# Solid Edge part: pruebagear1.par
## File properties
Author: there
Template: SEER_ExtSpurGear.par
Last saved by: there
Revision: 2
Application: Solid Edge
Density: 7833.000 kg/m^3
Accuracy: 0.990
SEER_Parameters: SEERSG2#ER#3#ER#0.349065850398866#ER#0.003#ER#0.05#ER#0#ER#0.0002#ER#0#ER#1#ER#1.2#ER#0.8#ER#10000#ER#1#ER#1#ER#30#ER#90#ER#0.01#ER#0.02#ER#0.03#ER#0.03#ER#0#ER#0#ER#1000#ER#1000#ER#104.71975511966#ER#104.71975511966#ER#9.54#ER#9.54#ER#0.92#ER#1#ER#1#ER#1#ER#1#ER#0#ER#0#ER#1#ER#0#ER#0#ER#1#ER#0#ER#0#ER#0.08#ER#0.08#ER#0.008#ER#0.008#ER#0.025#ER#0.025#ER#0#ER#1140#ER#605#ER#0#ER#1140#ER#390#ER#11#ER#SweptProtrusion_1#ER#Pattern_1#ER#SweptProtrusion_1#ER#Pattern_1#ER##ER#C:\Users\there\Documents\CarroInertia\pruebagear2.par#ER#0#ER#0#ER#ExtrudedProtrusion_4#ER#ExtrudedCutout_5#ER#ExtrudedProtrusion_4#ER#ExtrudedCutout_5#ER#0#ER#1#ER#0#ER#0#ER#False#ER#0
Username: there
Material: Steel
Face Style: Steel
Fill Style: ANSI32(Steel)
Virtual Style: Machined steel
Coef. of Thermal Exp: 1.3e-05
Thermal Conductivity: 32.0
Specific Heat: 481.0
Modulus of Elasticity: 199947953000.0
Poission's Ratio: 0.29
Yield Stress: 262000766.0
Ultimate Stress: 358527364.0
Elongation: 0.0
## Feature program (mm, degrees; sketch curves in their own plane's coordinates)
sketch for "unnamed Protrusion 1" plane through (0, 0, 0) normal (0, 0, 1) x-axis (1, 0, 0)
  circle centre (0, 0) radius 11.027
extrude "unnamed Protrusion 1" add finite 30 along +normal
sketch for "unnamed Cutout 1" plane through (0, 0, 30) normal (0, 0, 1) x-axis (0, 1, 0)
extrude "unnamed Cutout 1" cut through along -normal
swept protrusion "ProtrusiónPorBarrido_1"
pattern "unnamed Pattern 1" of "ProtrusiónPorBarrido_1"
swept protrusion "unnamed SweptProtrusion 1"
swept protrusion "unnamed SweptProtrusion 2"
swept protrusion "unnamed SweptProtrusion 3"
swept protrusion "unnamed SweptProtrusion 4"
swept protrusion "unnamed SweptProtrusion 5"
swept protrusion "unnamed SweptProtrusion 6"
swept protrusion "unnamed SweptProtrusion 7"
swept protrusion "unnamed SweptProtrusion 8"
swept protrusion "unnamed SweptProtrusion 9"
swept protrusion "unnamed SweptProtrusion 10"
swept protrusion "unnamed SweptProtrusion 11"
swept protrusion "unnamed SweptProtrusion 12"
swept protrusion "unnamed SweptProtrusion 13"
swept protrusion "unnamed SweptProtrusion 14"
swept protrusion "unnamed SweptProtrusion 15"
swept protrusion "unnamed SweptProtrusion 16"
swept protrusion "unnamed SweptProtrusion 17"
swept protrusion "unnamed SweptProtrusion 18"
swept protrusion "unnamed SweptProtrusion 19"
base feature "unnamed BaseFeature 1"
sketch for "ProtrusiónExtruida_4" plane through (0, 0, 0) normal (0, 0, 1) x-axis (1, 0, 0)
  circle centre (0, 0) radius 12.5
extrude "ProtrusiónExtruida_4" add finite 30 along +normal
sketch for "VaciadoExtruido_5" plane through (0, 0, 0) normal (0, 0, 1) x-axis (1, 0, 0)
  circle centre (0, 0) radius 12.5
extrude "VaciadoExtruido_5" cut finite 30 along +normal
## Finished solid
Body 1: sheet body, 1 face, 2 edges, 0 vertices.
  Faces by surface: cylinder 1
  Edges by curve: circle 2
Body 2: solid body, 123 faces, 362 edges, 240 vertices.
  Faces by surface: spline 100, cylinder 21, plane 2
  Edges by curve: circle 162, spline 160, intersection 36, line 4
Bounding box of the edges (mm; curved faces can reach further): 27.679 x 27.679 x 30.000, from (-13.8395, -13.8395, 0) to (13.8395, 13.8395, 30).
Cylindrical faces by radius (mm): R5 x1, R11.027 x20, R12.5 x1
Planar faces by outward normal: +z 1, -z 1
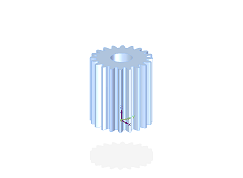
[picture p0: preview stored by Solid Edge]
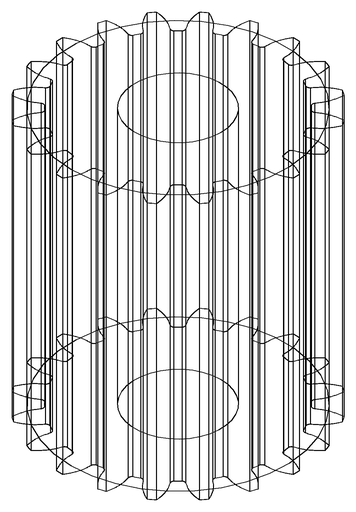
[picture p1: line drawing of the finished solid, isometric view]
